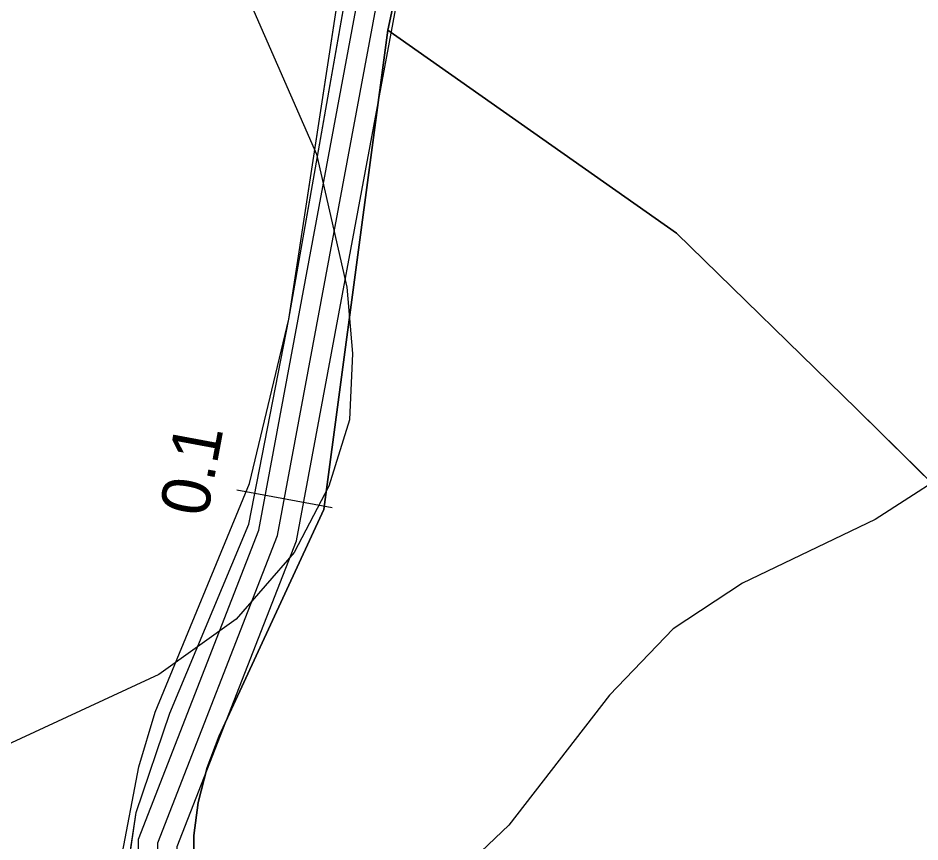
# Model space of a CAD drawing. Extents: x -662620 to -656370, y -1067090 to -1062990.
# Drawn here: x -661469.9 to -661376.8, y -1066196 to -1066111 of the extents above; entities that cross this region are included whole.
import ezdxf

# ---------------------------------------------------------------- set-up
doc = ezdxf.new("R2010")
doc.units = 0
for name, color, linetype in [('CESTA_ZABOR', 7, 'Continuous'), ('Default', 7, 'Continuous'), ('OBVOD_PÚ', 7, 'Continuous'), ('ORNÁ_PŮDA_-_STÁVAJÍCÍ', 7, 'Continuous'), ('OSTATNÍ_PLOCHA_-_STÁVAJÍCÍ', 7, 'Continuous'), ('POLNÍ_CESTA_STÁVAJÍCÍ_-_KRAJ', 7, 'Continuous'), ('POLNÍ_CESTA_STÁVAJÍCÍ_-_OSA', 7, 'Continuous'), ('VRSTEVNICE_ZÁKLADNÍ', 7, 'Continuous')]:
    doc.layers.add(name, color=color, linetype=linetype)

msp = doc.modelspace()

# ---------------------------------------------------------------- linework, layer by layer
at = {"layer": 'CESTA_ZABOR'}
for p, q in [((-661441.9, -1066142.09), (-661431.44, -1066082.732)), ((-661428.69, -1066098.31), (-661431.7, -1066112.27)), ((-661431.7, -1066112.27), (-661438.28, -1066161.75)), ((-661446.043, -1066163.256), (-661441.9, -1066142.09)), ((-661438.28, -1066161.75), (-661449.09, -1066185.1)), ((-661454.196, -1066182.771), (-661446.043, -1066163.256)), ((-661457.642, -1066193.015), (-661454.196, -1066182.771)), ((-661449.09, -1066185.1), (-661450.32, -1066188.36)), ((-661450.32, -1066188.36), (-661451.27, -1066191.99)), ((-661451.27, -1066191.99), (-661451.71, -1066195.38)), ((-661458.436, -1066198.247), (-661457.642, -1066193.015)), ((-661451.71, -1066195.38), (-661451.71, -1066209.69))]:
    msp.add_line(p, q, dxfattribs=at)
msp.add_lwpolyline([(-661413.39, -1066036.44), (-661414.41, -1066040.61), (-661418.7, -1066050.36), (-661425.38, -1066082.39), (-661428.69, -1066098.31), (-661431.7, -1066112.27), (-661438.28, -1066161.75), (-661449.09, -1066185.1), (-661450.32, -1066188.36), (-661451.27, -1066191.99), (-661451.71, -1066195.38), (-661451.71, -1066209.69), (-661453.466, -1066254.69), (-661458.39, -1066254.968), (-661458.08, -1066241.225), (-661458.436, -1066198.247), (-661457.642, -1066193.015), (-661454.196, -1066182.771), (-661446.043, -1066163.256), (-661441.9, -1066142.09), (-661431.44, -1066082.732), (-661422.518, -1066040.933), (-661419.247, -1066028.719), (-661412.46, -1066028.951)], close=True, dxfattribs=at)
at = {"layer": 'OBVOD_PÚ'}
for points in [[(-661441.9, -1066142.09), (-661432.53, -1066081.06)], [(-661438.28, -1066161.75), (-661431.7, -1066112.27)], [(-661431.7, -1066112.27), (-661401.88, -1066133.22)], [(-661401.88, -1066133.22), (-661383.27, -1066151.4)], [(-661445.97, -1066159.04), (-661441.9, -1066142.09)], [(-661372.12, -1066162.39), (-661383.27, -1066151.4)], [(-661455.71, -1066182.65), (-661445.97, -1066159.04)], [(-661449.09, -1066185.1), (-661438.28, -1066161.75)], [(-661457.4, -1066188.29), (-661455.71, -1066182.65)], [(-661450.32, -1066188.36), (-661449.09, -1066185.1)], [(-661459.19, -1066197.87), (-661457.4, -1066188.29)], [(-661451.27, -1066191.99), (-661450.32, -1066188.36)], [(-661451.71, -1066195.38), (-661451.27, -1066191.99)], [(-661451.71, -1066209.69), (-661451.71, -1066195.38)]]:
    msp.add_lwpolyline(points, dxfattribs=at)
at = {"layer": 'ORNÁ_PŮDA_-_STÁVAJÍCÍ'}
for p, q in [((-661431.7, -1066112.27), (-661428.69, -1066098.31)), ((-661401.88, -1066133.22), (-661431.7, -1066112.27)), ((-661383.27, -1066151.4), (-661401.88, -1066133.22)), ((-661372.12, -1066162.39), (-661383.27, -1066151.4))]:
    msp.add_line(p, q, dxfattribs=at)
msp.add_lwpolyline([(-661214.96, -1066228.74), (-661247.14, -1066231.81), (-661258.89, -1066232.13), (-661267.57, -1066231.46), (-661276.97, -1066230.21), (-661286.21, -1066227.67), (-661305.57, -1066219.95), (-661349.81, -1066200.46), (-661372.12, -1066162.39), (-661383.27, -1066151.4), (-661401.88, -1066133.22), (-661431.7, -1066112.27), (-661428.69, -1066098.31)], dxfattribs=at)
at = {"layer": 'OSTATNÍ_PLOCHA_-_STÁVAJÍCÍ'}
for p, q in [((-661441.9, -1066142.09), (-661432.53, -1066081.06)), ((-661441.9, -1066142.09), (-661432.53, -1066081.06)), ((-661428.69, -1066098.31), (-661431.7, -1066112.27)), ((-661428.69, -1066098.31), (-661431.7, -1066112.27)), ((-661431.7, -1066112.27), (-661438.28, -1066161.75)), ((-661431.7, -1066112.27), (-661438.28, -1066161.75)), ((-661445.97, -1066159.04), (-661441.9, -1066142.09)), ((-661445.97, -1066159.04), (-661441.9, -1066142.09)), ((-661455.71, -1066182.65), (-661445.97, -1066159.04)), ((-661455.71, -1066182.65), (-661445.97, -1066159.04)), ((-661438.28, -1066161.75), (-661449.09, -1066185.1)), ((-661438.28, -1066161.75), (-661449.09, -1066185.1)), ((-661457.4, -1066188.29), (-661455.71, -1066182.65)), ((-661457.4, -1066188.29), (-661455.71, -1066182.65)), ((-661449.09, -1066185.1), (-661450.32, -1066188.36)), ((-661449.09, -1066185.1), (-661450.32, -1066188.36)), ((-661459.19, -1066197.87), (-661457.4, -1066188.29)), ((-661459.19, -1066197.87), (-661457.4, -1066188.29)), ((-661450.32, -1066188.36), (-661451.27, -1066191.99)), ((-661450.32, -1066188.36), (-661451.27, -1066191.99)), ((-661451.27, -1066191.99), (-661451.71, -1066195.38)), ((-661451.27, -1066191.99), (-661451.71, -1066195.38)), ((-661451.71, -1066195.38), (-661451.71, -1066209.69)), ((-661451.71, -1066195.38), (-661451.71, -1066209.69))]:
    msp.add_line(p, q, dxfattribs=at)
msp.add_lwpolyline([(-661428.69, -1066098.31), (-661431.7, -1066112.27), (-661438.28, -1066161.75), (-661449.09, -1066185.1), (-661450.32, -1066188.36), (-661451.27, -1066191.99), (-661451.71, -1066195.38), (-661451.71, -1066209.69), (-661451.8, -1066254.74), (-661461.03, -1066249.07), (-661459.63, -1066242.23), (-661459.19, -1066197.87), (-661457.4, -1066188.29), (-661455.71, -1066182.65), (-661445.97, -1066159.04), (-661441.9, -1066142.09), (-661432.53, -1066081.06)], dxfattribs=at)
msp.add_lwpolyline([(-661428.69, -1066098.31), (-661431.7, -1066112.27), (-661438.28, -1066161.75), (-661449.09, -1066185.1), (-661450.32, -1066188.36), (-661451.27, -1066191.99), (-661451.71, -1066195.38), (-661451.71, -1066209.69), (-661451.8, -1066254.74), (-661461.03, -1066249.07), (-661459.63, -1066242.23), (-661459.19, -1066197.87), (-661457.4, -1066188.29), (-661455.71, -1066182.65), (-661445.97, -1066159.04), (-661441.9, -1066142.09), (-661432.53, -1066081.06)], dxfattribs=at)
at = {"layer": 'POLNÍ_CESTA_STÁVAJÍCÍ_-_KRAJ'}
for points in [[(-661457.689, -1066258.226), (-661457.417, -1066195.74), (-661444.987, -1066163.856), (-661424.306, -1066052.931), (-661418.114, -1066033.005), (-661415.384, -1066020.994), (-661408.949, -1066008.964), (-661400.027, -1065999.517), (-661398.291, -1065990.593), (-661398.021, -1065951.712), (-661379.329, -1065903.491), (-661370.678, -1065883.755), (-661362.205, -1065868.177), (-661350.856, -1065854.89), (-661335.545, -1065845.147), (-661315.743, -1065840.264), (-661299.747, -1065833.865)], [(-661453.689, -1066258.243), (-661453.42, -1066196.501), (-661441.124, -1066164.959), (-661420.417, -1066053.894), (-661414.248, -1066034.044), (-661411.602, -1066022.405), (-661405.674, -1066011.322), (-661396.322, -1066001.419), (-661394.294, -1065990.992), (-661394.027, -1065952.473), (-661375.631, -1065905.018), (-661367.082, -1065885.516), (-661358.892, -1065870.456), (-661348.203, -1065857.943), (-661333.951, -1065848.873), (-661314.516, -1065844.081), (-661298.261, -1065837.579)]]:
    msp.add_lwpolyline(points, dxfattribs=at)
at = {"layer": 'POLNÍ_CESTA_STÁVAJÍCÍ_-_OSA'}
for points in [[(-661455.689, -1066258.234), (-661455.418, -1066196.12), (-661443.056, -1066164.407), (-661422.362, -1066053.412), (-661416.181, -1066033.525), (-661413.493, -1066021.7), (-661407.312, -1066010.143), (-661398.174, -1066000.468), (-661396.293, -1065990.793), (-661396.024, -1065952.092), (-661377.48, -1065904.254), (-661368.88, -1065884.635), (-661360.549, -1065869.317), (-661349.53, -1065856.416), (-661334.748, -1065847.01), (-661315.129, -1065842.172), (-661299.004, -1065835.722)], [(-661447.266, -1066159.708), (-661437.435, -1066161.541)]]:
    msp.add_lwpolyline(points, dxfattribs=at)
at = {"layer": 'VRSTEVNICE_ZÁKLADNÍ'}
for points in [[(-661454.041, -1066090.821), (-661439.054, -1066125.079), (-661435.914, -1066138.781), (-661435.343, -1066145.633), (-661435.628, -1066152.484), (-661437.769, -1066159.336), (-661441.337, -1066166.187), (-661447.333, -1066173.038), (-661455.326, -1066178.748), (-661475.309, -1066188.026), (-661485.301, -1066193.45), (-661498.699, -1066204.351)], [(-661454.041, -1066090.821), (-661439.054, -1066125.079), (-661435.914, -1066138.781), (-661435.343, -1066145.633), (-661435.628, -1066152.484), (-661437.769, -1066159.336), (-661441.337, -1066166.187), (-661447.333, -1066173.038), (-661455.326, -1066178.748), (-661475.309, -1066188.026), (-661485.301, -1066193.45), (-661498.699, -1066204.351)], [(-661363.403, -1066106.237), (-661362.974, -1066136.212), (-661363.545, -1066145.062), (-661365.972, -1066150.2), (-661371.462, -1066156.38), (-661381.388, -1066162.761), (-661395.091, -1066169.327), (-661402.227, -1066174.038), (-661408.793, -1066180.889), (-661419.213, -1066194.306), (-661428.491, -1066203.156), (-661446.476, -1066213.719), (-661474.738, -1066228.421)], [(-661363.403, -1066106.237), (-661362.974, -1066136.212), (-661363.545, -1066145.062), (-661365.972, -1066150.2), (-661371.462, -1066156.38), (-661381.388, -1066162.761), (-661395.091, -1066169.327), (-661402.227, -1066174.038), (-661408.793, -1066180.889), (-661419.213, -1066194.306), (-661428.491, -1066203.156), (-661446.476, -1066213.719), (-661474.738, -1066228.421)]]:
    msp.add_lwpolyline(points, dxfattribs=at)

# ---------------------------------------------------------------- texts
at = {"layer": 'Default'}
msp.add_text('0.1', height=5, rotation=79.43899, dxfattribs=at).set_placement((-661450.356, -1066162.643))

doc.saveas('drawing.dxf')
